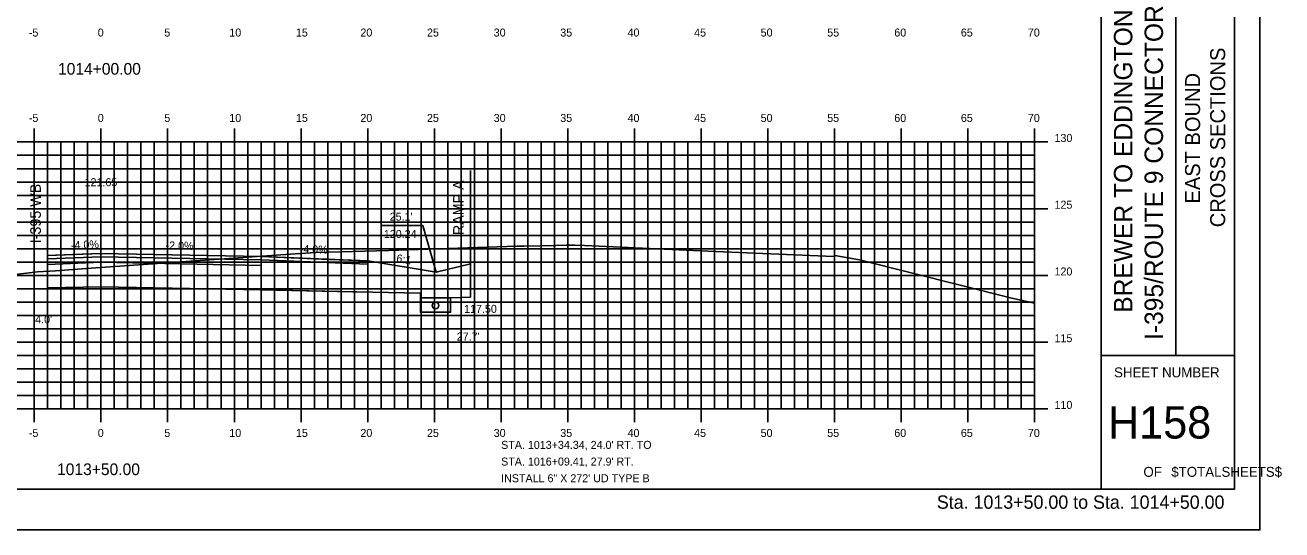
# Model space of a CAD drawing. Extents: x 852847 to 853019, y 365624 to 365734.
# Drawn here: x 852924.6 to 853018.9, y 365624 to 365661.8 of the extents above; entities that cross this region are included whole.
import ezdxf

# ---------------------------------------------------------------- set-up
doc = ezdxf.new("R2010")
doc.units = 0
for name, color, linetype in [('ANNOTATION', 7, 'Continuous'), ('BORDER', 7, 'Continuous'), ('D_Roadway_Centerline', 7, 'Continuous'), ('D_Roadway_Centerline_Text', 7, 'Continuous'), ('D_Roadway_Edge_Shoulder', 7, 'Continuous'), ('D_Roadway_Edge_TW', 7, 'Continuous'), ('D_Roadway_FinishedGrade', 7, 'Continuous'), ('D_Roadway_Pavement', 7, 'Continuous'), ('D_Roadway_SubGrade', 7, 'Continuous'), ('D_Text_Standard', 7, 'Continuous'), ('H_V ANNOTATION', 7, 'Continuous'), ('M_Roadway_Centerline', 7, 'Continuous'), ('MAJOR', 7, 'Continuous'), ('MINOR', 7, 'Continuous'), ('PDRAIN', 7, 'Continuous'), ('PLOT BOUNDARY', 7, 'Continuous'), ('S_Roadway_Centerline', 7, 'Continuous')]:
    doc.layers.add(name, color=color, linetype=linetype)

msp = doc.modelspace()

# ---------------------------------------------------------------- linework, layer by layer
at = {"layer": 'ANNOTATION'}
msp.add_lwpolyline([(852951.327, 365646.769), (852954.437, 365646.769), (852955.448, 365643.264)], dxfattribs=at)
at = {"layer": 'BORDER'}
for p, q in [((853005.305, 365627.027), (853005.305, 365732.027)), ((853010.896, 365637.03), (853010.896, 365672.03)), ((853005.305, 365637.03), (853015.305, 365637.03))]:
    msp.add_line(p, q, dxfattribs=at)
msp.add_lwpolyline([(852855.305, 365627.027), (853015.305, 365627.027), (853015.305, 365732.027), (852855.305, 365732.027)], close=True, dxfattribs=at)
at = {"layer": 'D_Roadway_Centerline'}
for p, q in [((852958.017, 365643.905), (852958.017, 365641.405)), ((852942.305, 365641.941), (852954.264, 365641.702)), ((852956.514, 365641.345), (852954.264, 365641.345))]:
    msp.add_line(p, q, dxfattribs=at)
for points in [[(852926.305, 365644.521), (852926.305, 365644.521), (852928.196, 365644.596), (852930.303, 365644.681), (852930.305, 365644.681), (852942.298, 365644.441), (852942.305, 365644.441), (852947.441, 365644.235), (852950.305, 365644.121)], [(852950.305, 365644.121), (852955.448, 365643.264), (852958.017, 365643.905)], [(852958.017, 365641.405), (852956.514, 365641.345)]]:
    msp.add_lwpolyline(points, dxfattribs=at)
at = {"layer": 'D_Roadway_Edge_Shoulder'}
for points in [[(852930.305, 365644.681), (852926.305, 365644.521), (852926.305, 365644.271), (852930.305, 365644.431)], [(852942.305, 365644.441), (852950.305, 365644.121), (852950.305, 365643.871), (852942.305, 365644.191)]]:
    msp.add_lwpolyline(points, close=True, dxfattribs=at)
at = {"layer": 'D_Roadway_Edge_TW'}
msp.add_lwpolyline([(852930.305, 365644.681), (852942.305, 365644.441), (852942.305, 365644.191), (852930.305, 365644.431)], close=True, dxfattribs=at)
msp.add_lwpolyline([(852942.305, 365644.441), (852942.305, 365644.275)], dxfattribs=at)
at = {"layer": 'D_Roadway_FinishedGrade'}
for p, q in [((852930.305, 365644.681), (852930.305, 365644.431)), ((852926.305, 365644.521), (852926.305, 365644.271)), ((852942.305, 365644.441), (852942.305, 365644.191)), ((852950.305, 365644.121), (852950.305, 365643.871))]:
    msp.add_line(p, q, dxfattribs=at)
at = {"layer": 'D_Roadway_Pavement'}
for points in [[(852930.305, 365644.431), (852926.305, 365644.271), (852926.305, 365643.855), (852930.305, 365644.015)], [(852930.305, 365644.431), (852942.305, 365644.191), (852942.305, 365643.775), (852930.305, 365644.015)]]:
    msp.add_lwpolyline(points, close=True, dxfattribs=at)
msp.add_lwpolyline([(852942.305, 365644.275), (852942.305, 365643.775)], dxfattribs=at)
msp.add_lwpolyline([(852942.305, 365644.275), (852942.305, 365643.775)], dxfattribs=at)
at = {"layer": 'D_Roadway_SubGrade'}
for p, q in [((852926.305, 365650.425), (852926.305, 365642.101)), ((852958.017, 365650.892), (852958.017, 365641.405))]:
    msp.add_line(p, q, dxfattribs=at)
for points in [[(852930.305, 365644.015), (852926.305, 365643.855), (852926.305, 365644.355), (852926.305, 365644.521), (852926.305, 365642.101), (852930.305, 365642.181)], [(852930.305, 365644.015), (852942.305, 365643.775), (852942.305, 365641.941), (852930.305, 365642.181)], [(852942.305, 365643.775), (852942.305, 365644.191), (852950.305, 365643.871), (852950.305, 365644.121), (852950.305, 365641.781), (852942.305, 365641.941)]]:
    msp.add_lwpolyline(points, close=True, dxfattribs=at)
msp.add_lwpolyline([(852942.305, 365643.775), (852942.305, 365641.941)], dxfattribs=at)
at = {"layer": 'MAJOR'}
for p, q in [((852925.305, 365654.029), (852925.305, 365653.027)), ((852930.305, 365654.029), (852930.305, 365653.027)), ((852935.305, 365654.029), (852935.305, 365653.027)), ((852940.305, 365654.029), (852940.305, 365653.027)), ((852945.305, 365654.029), (852945.305, 365653.027)), ((852950.305, 365654.029), (852950.305, 365653.027)), ((852955.305, 365654.029), (852955.305, 365653.027)), ((852960.305, 365654.029), (852960.305, 365653.027)), ((852965.305, 365654.029), (852965.305, 365653.027)), ((852970.305, 365654.029), (852970.305, 365653.027)), ((852975.305, 365654.029), (852975.305, 365653.027)), ((852980.305, 365654.029), (852980.305, 365653.027)), ((852985.305, 365654.029), (852985.305, 365653.027)), ((852990.305, 365654.029), (852990.305, 365653.027)), ((852995.305, 365654.029), (852995.305, 365653.027)), ((853000.305, 365654.029), (853000.305, 365653.027)), ((852860.305, 365653.027), (853000.305, 365653.027)), ((852860.305, 365653.027), (853000.305, 365653.027)), ((852925.305, 365633.027), (852925.305, 365653.027)), ((852930.305, 365633.027), (852930.305, 365653.027)), ((852935.305, 365633.027), (852935.305, 365653.027)), ((852940.305, 365633.027), (852940.305, 365653.027)), ((852945.305, 365633.027), (852945.305, 365653.027)), ((852950.305, 365633.027), (852950.305, 365653.027)), ((852955.305, 365633.027), (852955.305, 365653.027)), ((852960.305, 365633.027), (852960.305, 365653.027)), ((852965.305, 365633.027), (852965.305, 365653.027)), ((852970.305, 365633.027), (852970.305, 365653.027)), ((852975.305, 365633.027), (852975.305, 365653.027)), ((852980.305, 365633.027), (852980.305, 365653.027)), ((852985.305, 365633.027), (852985.305, 365653.027)), ((852990.305, 365633.027), (852990.305, 365653.027)), ((852995.305, 365633.027), (852995.305, 365653.027)), ((853001.307, 365653.027), (852999.303, 365653.027)), ((853000.305, 365633.027), (853000.305, 365653.027)), ((853000.305, 365633.027), (853000.305, 365653.027)), ((852860.305, 365648.027), (853000.305, 365648.027)), ((853001.307, 365648.027), (852999.303, 365648.027)), ((852860.305, 365643.027), (853000.305, 365643.027)), ((853001.307, 365643.027), (852999.303, 365643.027)), ((852860.305, 365638.027), (853000.305, 365638.027)), ((853001.307, 365638.027), (852999.303, 365638.027)), ((852860.305, 365633.027), (853000.305, 365633.027)), ((852860.305, 365633.027), (853000.305, 365633.027)), ((852925.305, 365632.025), (852925.305, 365633.027)), ((852930.305, 365632.025), (852930.305, 365633.027)), ((852935.305, 365632.025), (852935.305, 365633.027)), ((852940.305, 365632.025), (852940.305, 365633.027)), ((852945.305, 365632.025), (852945.305, 365633.027)), ((852950.305, 365632.025), (852950.305, 365633.027)), ((852955.305, 365632.025), (852955.305, 365633.027)), ((852960.305, 365632.025), (852960.305, 365633.027)), ((852965.305, 365632.025), (852965.305, 365633.027)), ((852970.305, 365632.025), (852970.305, 365633.027)), ((852975.305, 365632.025), (852975.305, 365633.027)), ((852980.305, 365632.025), (852980.305, 365633.027)), ((852985.305, 365632.025), (852985.305, 365633.027)), ((852990.305, 365632.025), (852990.305, 365633.027)), ((852995.305, 365632.025), (852995.305, 365633.027)), ((853001.307, 365633.027), (852999.303, 365633.027)), ((853000.305, 365632.025), (853000.305, 365633.027))]:
    msp.add_line(p, q, dxfattribs=at)
at = {"layer": 'MINOR'}
for p, q in [((852926.305, 365633.027), (852926.305, 365653.027)), ((852927.305, 365633.027), (852927.305, 365653.027)), ((852928.305, 365633.027), (852928.305, 365653.027)), ((852929.305, 365633.027), (852929.305, 365653.027)), ((852931.305, 365633.027), (852931.305, 365653.027)), ((852932.305, 365633.027), (852932.305, 365653.027)), ((852933.305, 365633.027), (852933.305, 365653.027)), ((852934.305, 365633.027), (852934.305, 365653.027)), ((852936.305, 365633.027), (852936.305, 365653.027)), ((852937.305, 365633.027), (852937.305, 365653.027)), ((852938.305, 365633.027), (852938.305, 365653.027)), ((852939.305, 365633.027), (852939.305, 365653.027)), ((852941.305, 365633.027), (852941.305, 365653.027)), ((852942.305, 365633.027), (852942.305, 365653.027)), ((852943.305, 365633.027), (852943.305, 365653.027)), ((852944.305, 365633.027), (852944.305, 365653.027)), ((852946.305, 365633.027), (852946.305, 365653.027)), ((852947.305, 365633.027), (852947.305, 365653.027)), ((852948.305, 365633.027), (852948.305, 365653.027)), ((852949.305, 365633.027), (852949.305, 365653.027)), ((852951.305, 365633.027), (852951.305, 365653.027)), ((852952.305, 365633.027), (852952.305, 365653.027)), ((852953.305, 365633.027), (852953.305, 365653.027)), ((852954.305, 365633.027), (852954.305, 365653.027)), ((852956.305, 365633.027), (852956.305, 365653.027)), ((852957.305, 365633.027), (852957.305, 365653.027)), ((852958.305, 365633.027), (852958.305, 365653.027)), ((852959.305, 365633.027), (852959.305, 365653.027)), ((852961.305, 365633.027), (852961.305, 365653.027)), ((852962.305, 365633.027), (852962.305, 365653.027)), ((852963.305, 365633.027), (852963.305, 365653.027)), ((852964.305, 365633.027), (852964.305, 365653.027)), ((852966.305, 365633.027), (852966.305, 365653.027)), ((852967.305, 365633.027), (852967.305, 365653.027)), ((852968.305, 365633.027), (852968.305, 365653.027)), ((852969.305, 365633.027), (852969.305, 365653.027)), ((852971.305, 365633.027), (852971.305, 365653.027)), ((852972.305, 365633.027), (852972.305, 365653.027)), ((852973.305, 365633.027), (852973.305, 365653.027)), ((852974.305, 365633.027), (852974.305, 365653.027)), ((852976.305, 365633.027), (852976.305, 365653.027)), ((852977.305, 365633.027), (852977.305, 365653.027)), ((852978.305, 365633.027), (852978.305, 365653.027)), ((852979.305, 365633.027), (852979.305, 365653.027)), ((852981.305, 365633.027), (852981.305, 365653.027)), ((852982.305, 365633.027), (852982.305, 365653.027)), ((852983.305, 365633.027), (852983.305, 365653.027)), ((852984.305, 365633.027), (852984.305, 365653.027)), ((852986.305, 365633.027), (852986.305, 365653.027)), ((852987.305, 365633.027), (852987.305, 365653.027)), ((852988.305, 365633.027), (852988.305, 365653.027)), ((852989.305, 365633.027), (852989.305, 365653.027)), ((852991.305, 365633.027), (852991.305, 365653.027)), ((852992.305, 365633.027), (852992.305, 365653.027)), ((852993.305, 365633.027), (852993.305, 365653.027)), ((852994.305, 365633.027), (852994.305, 365653.027)), ((852996.305, 365633.027), (852996.305, 365653.027)), ((852997.305, 365633.027), (852997.305, 365653.027)), ((852998.305, 365633.027), (852998.305, 365653.027)), ((852999.305, 365633.027), (852999.305, 365653.027)), ((852860.305, 365652.027), (853000.305, 365652.027)), ((853000.305, 365652.027), (852999.303, 365652.027)), ((852860.305, 365651.027), (853000.305, 365651.027)), ((853000.305, 365651.027), (852999.303, 365651.027)), ((852860.305, 365650.027), (853000.305, 365650.027)), ((853000.305, 365650.027), (852999.303, 365650.027)), ((852860.305, 365649.027), (853000.305, 365649.027)), ((853000.305, 365649.027), (852999.303, 365649.027)), ((852860.305, 365647.027), (853000.305, 365647.027)), ((853000.305, 365647.027), (852999.303, 365647.027)), ((852860.305, 365646.027), (853000.305, 365646.027)), ((853000.305, 365646.027), (852999.303, 365646.027)), ((852860.305, 365645.027), (853000.305, 365645.027)), ((853000.305, 365645.027), (852999.303, 365645.027)), ((852860.305, 365644.027), (853000.305, 365644.027)), ((853000.305, 365644.027), (852999.303, 365644.027)), ((852860.305, 365642.027), (853000.305, 365642.027)), ((853000.305, 365642.027), (852999.303, 365642.027)), ((852860.305, 365641.027), (853000.305, 365641.027)), ((853000.305, 365641.027), (852999.303, 365641.027)), ((852860.305, 365640.027), (853000.305, 365640.027)), ((853000.305, 365640.027), (852999.303, 365640.027)), ((852860.305, 365639.027), (853000.305, 365639.027)), ((853000.305, 365639.027), (852999.303, 365639.027)), ((852860.305, 365637.027), (853000.305, 365637.027)), ((853000.305, 365637.027), (852999.303, 365637.027)), ((852860.305, 365636.027), (853000.305, 365636.027)), ((853000.305, 365636.027), (852999.303, 365636.027)), ((852860.305, 365635.027), (853000.305, 365635.027)), ((853000.305, 365635.027), (852999.303, 365635.027)), ((852860.305, 365634.027), (853000.305, 365634.027)), ((853000.305, 365634.027), (852999.303, 365634.027))]:
    msp.add_line(p, q, dxfattribs=at)
at = {"layer": 'PDRAIN'}
msp.add_lwpolyline([(852954.264, 365641.702), (852954.264, 365640.276), (852956.514, 365640.276), (852956.514, 365641.345)], dxfattribs=at)
msp.add_circle((852955.389, 365640.776), 0.25, dxfattribs=at)
at = {"layer": 'PLOT BOUNDARY'}
msp.add_lwpolyline([(852847.212, 365623.968), (853017.212, 365623.968), (853017.212, 365733.968), (852847.212, 365733.968)], close=True, dxfattribs=at)
at = {"layer": 'S_Roadway_Centerline'}
msp.add_lwpolyline([(852913.178, 365641.884), (852924.71, 365643.199), (852925.537, 365643.29), (852926.887, 365643.38), (852929.229, 365643.546), (852944.877, 365644.648), (852946.435, 365644.74), (852951.885, 365644.9), (852961.499, 365645.226), (852962.048, 365645.234), (852964.4, 365645.282), (852965.203, 365645.297), (852965.742, 365645.298), (852965.801, 365645.301), (852966.568, 365645.278), (852975.806, 365644.845), (852985.253, 365644.449), (852985.334, 365644.515), (852987.173, 365644.197), (852998.616, 365641.317), (853000.305, 365640.942)], dxfattribs=at)

# ---------------------------------------------------------------- texts
at = {"layer": 'ANNOTATION'}
for s, height, rotation, p in [('I-395 WB', 0.8, 90, (852925.798, 365645.439)), ('RAMP A', 0.8, 90, (852957.51, 365646.052)), ("25.1' ", 0.6, 360, (852951.957, 365647.132)), ('120.24', 0.6, 360, (852951.516, 365645.832)), ('-4.0%', 0.6, 2.29043, (852928.065, 365644.992)), ('-2.0%', 0.6, 358.85424, (852935.145, 365644.984)), ('-4.0%', 0.6, 357.70931, (852945.201, 365644.726)), ('6:1', 0.6, 350.53768, (852952.422, 365644.038))]:
    msp.add_text(s, height=height, rotation=rotation, dxfattribs=at).set_placement(p)
at = {"layer": 'BORDER'}
for s, height, p in [('BREWER TO EDDINGTON', 1.37787, (853007.639, 365640.231)), ('I-395/ROUTE 9 CONNECTOR', 1.37787, (853009.94, 365638.192)), ('CROSS SECTIONS', 1.125, (853014.602, 365646.638)), ('EAST BOUND', 1.125, (853012.723, 365648.418))]:
    msp.add_text(s, height=height, rotation=90, dxfattribs=at).set_placement(p)
for s, height, p in [('SHEET NUMBER', 0.74527, (853006.271, 365635.393)), ('H158', 2.4194, (853005.82, 365630.809)), ('OF', 0.7453, (853008.472, 365627.94)), ('$TOTALSHEETS$', 0.74527, (853010.562, 365627.94))]:
    msp.add_text(s, height=height, dxfattribs=at).set_placement(p)
at = {"layer": 'D_Roadway_Centerline'}
for s, p in [('C', (852930.3, 365644.681)), ('L', (852930.305, 365644.673))]:
    msp.add_text(s, height=0.0146, dxfattribs=at).set_placement(p)
at = {"layer": 'D_Roadway_Centerline_Text'}
msp.add_text('121.65', height=0.6, dxfattribs=at).set_placement((852929.077, 365649.713))
at = {"layer": 'D_Text_Standard'}
for s, p in [('117.50', (852957.535, 365640.226)), ("4.0'", (852925.371, 365639.435)), ("27.7'", (852956.981, 365638.15)), ("STA. 1013+34.34, 24.0' RT. TO ", (852960.311, 365630.033)), ("STA. 1016+09.41, 27.9' RT.", (852960.311, 365628.783)), ('INSTALL 6" X 272\' UD TYPE B', (852960.311, 365627.533))]:
    msp.add_text(s, height=0.6, dxfattribs=at).set_placement(p)
at = {"layer": 'H_V ANNOTATION'}
for s, height, p in [('-5', 0.6, (852924.896, 365660.927)), ('0', 0.6, (852930.064, 365660.927)), ('5', 0.6, (852935.056, 365660.927)), ('10', 0.6, (852939.93, 365660.927)), ('15', 0.6, (852944.922, 365660.927)), ('20', 0.6, (852949.759, 365660.927)), ('25', 0.6, (852954.751, 365660.927)), ('30', 0.6, (852959.754, 365660.927)), ('35', 0.6, (852964.746, 365660.927)), ('40', 0.6, (852969.791, 365660.927)), ('45', 0.6, (852974.783, 365660.927)), ('50', 0.6, (852979.77, 365660.927)), ('55', 0.6, (852984.762, 365660.927)), ('60', 0.6, (852989.791, 365660.927)), ('65', 0.6, (852994.783, 365660.927)), ('70', 0.6, (852999.807, 365660.927)), ('1014+00.00', 0.875, (852927.082, 365658.07)), ('-5', 0.6, (852924.896, 365654.527)), ('0', 0.6, (852930.064, 365654.527)), ('5', 0.6, (852935.056, 365654.527)), ('10', 0.6, (852939.93, 365654.527)), ('15', 0.6, (852944.922, 365654.527)), ('20', 0.6, (852949.759, 365654.527)), ('25', 0.6, (852954.751, 365654.527)), ('30', 0.6, (852959.754, 365654.527)), ('35', 0.6, (852964.746, 365654.527)), ('40', 0.6, (852969.791, 365654.527)), ('45', 0.6, (852974.783, 365654.527)), ('50', 0.6, (852979.77, 365654.527)), ('55', 0.6, (852984.762, 365654.527)), ('60', 0.6, (852989.791, 365654.527)), ('65', 0.6, (852994.783, 365654.527)), ('70', 0.6, (852999.807, 365654.527)), ('130', 0.6, (853001.805, 365653.027)), ('125', 0.6, (853001.805, 365648.027)), ('120', 0.6, (853001.805, 365643.027)), ('115', 0.6, (853001.805, 365638.027)), ('110', 0.6, (853001.805, 365633.027)), ('-5', 0.6, (852924.896, 365630.927)), ('0', 0.6, (852930.064, 365630.927)), ('5', 0.6, (852935.056, 365630.927)), ('10', 0.6, (852939.93, 365630.927)), ('15', 0.6, (852944.922, 365630.927)), ('20', 0.6, (852949.759, 365630.927)), ('25', 0.6, (852954.751, 365630.927)), ('30', 0.6, (852959.754, 365630.927)), ('35', 0.6, (852964.746, 365630.927)), ('40', 0.6, (852969.791, 365630.927)), ('45', 0.6, (852974.783, 365630.927)), ('50', 0.6, (852979.77, 365630.927)), ('55', 0.6, (852984.762, 365630.927)), ('60', 0.6, (852989.791, 365630.927)), ('65', 0.6, (852994.783, 365630.927)), ('70', 0.6, (852999.807, 365630.927)), ('1013+50.00', 0.875, (852927.012, 365628.07)), ('Sta. 1013+50.00 to Sta. 1014+50.00', 1.0002, (852992.981, 365625.547))]:
    msp.add_text(s, height=height, dxfattribs=at).set_placement(p)
at = {"layer": 'M_Roadway_Centerline'}
for s, p in [('C', (852961.494, 365645.226)), ('L', (852961.499, 365645.219)), ('C', (852965.795, 365645.301)), ('L', (852965.801, 365645.294))]:
    msp.add_text(s, height=0.0146, dxfattribs=at).set_placement(p)

doc.saveas('drawing.dxf')
